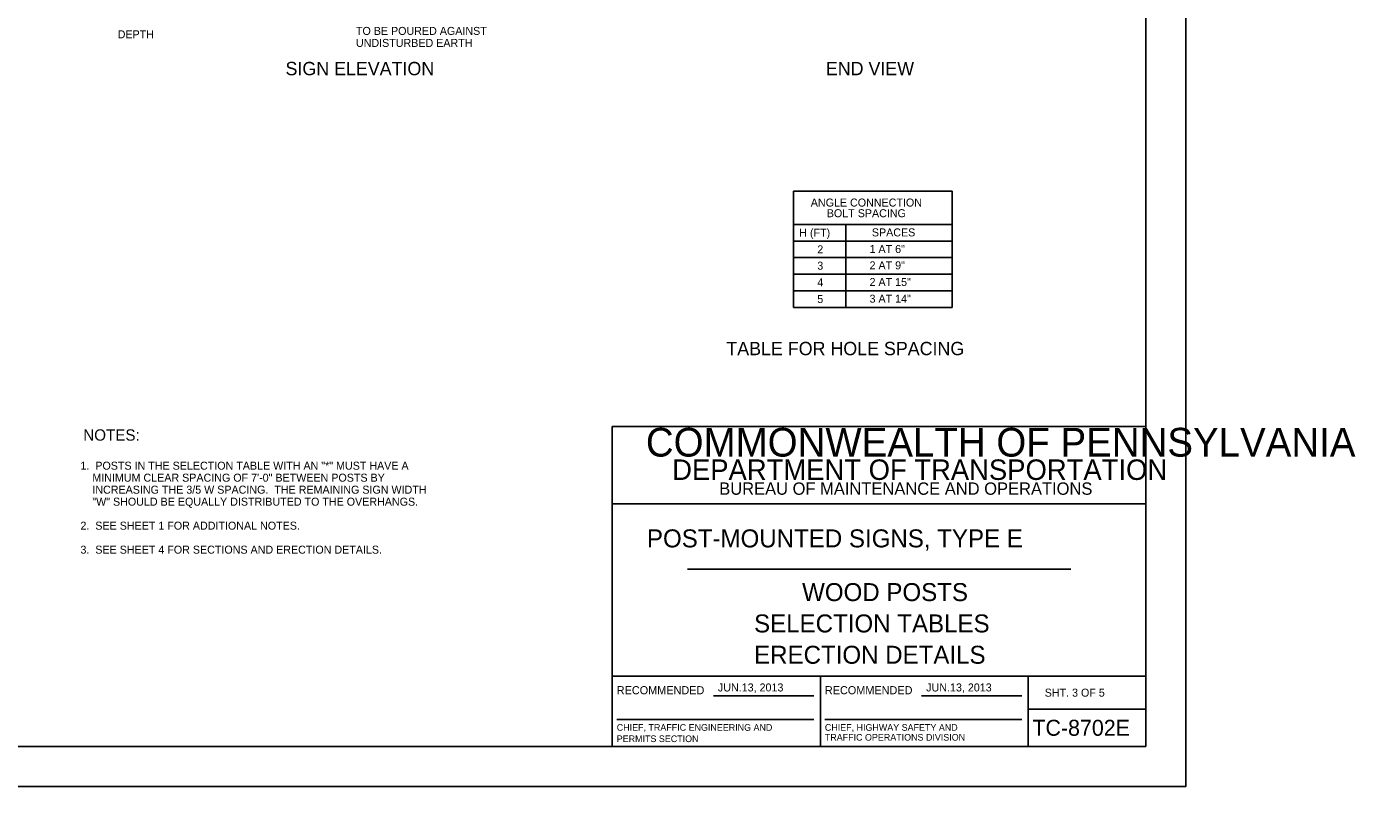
# Model space of a CAD drawing. Extents: x -2340 to 628, y -879 to 309.
# Drawn here: x 130.1 to 628.2, y -284.6 to 0.5 of the extents above; entities that cross this region are included whole.
import ezdxf

# ---------------------------------------------------------------- set-up
doc = ezdxf.new("R2010")
doc.units = 0
for name, color, linetype in [('Level 1', 7, 'Continuous'), ('Level 2', 7, 'Continuous'), ('Level 3', 7, 'Continuous'), ('Level 4', 7, 'Continuous'), ('PLT-BNDY', 7, 'Continuous')]:
    doc.layers.add(name, color=color, linetype=linetype)

msp = doc.modelspace()

# ---------------------------------------------------------------- linework, layer by layer
at = {"layer": 'Level 1'}
for p, q in [((549.61, -269.56), (549.61, 294.44)), ((349.61, -269.56), (349.61, -149.56)), ((349.61, -149.56), (549.61, -149.56)), ((549.61, -178.56), (349.61, -178.56)), ((377.86, -203.06), (521.49, -203.06)), ((349.61, -243.19), (549.61, -243.19)), ((427.61, -243.19), (427.61, -269.56)), ((505.49, -269.56), (505.49, -243.19)), ((387.55, -250.62), (425.17, -250.62)), ((465.55, -250.62), (503.17, -250.62)), ((505.49, -255.56), (549.61, -255.56)), ((351.3, -259.51), (425.17, -259.51)), ((429.3, -259.51), (503.17, -259.51)), ((549.61, -269.56), (-236.39, -269.56)), ((-236.39, -269.56), (349.61, -269.56))]:
    msp.add_line(p, q, dxfattribs=at)
at = {"layer": 'Level 2'}
for p, q in [((477.05, -61.22), (417.55, -61.22)), ((417.55, -104.84), (417.55, -61.22)), ((477.05, -104.84), (477.05, -61.22)), ((477.05, -73.72), (417.55, -73.72)), ((437.11, -104.84), (437.11, -73.72)), ((477.05, -79.97), (417.55, -79.97)), ((477.05, -86.09), (417.55, -86.09)), ((477.05, -92.34), (417.55, -92.34)), ((477.05, -98.59), (417.55, -98.59)), ((477.05, -104.84), (417.55, -104.84))]:
    msp.add_line(p, q, dxfattribs=at)
at = {"layer": 'PLT-BNDY'}
msp.add_lwpolyline([(-276.39, 309.44), (564.61, 309.44), (564.61, -284.56), (-276.39, -284.56)], close=True, dxfattribs=at)

# ---------------------------------------------------------------- texts
at = {"layer": 'Level 1'}
for s, height, p in [('COMMONWEALTH OF PENNSYLVANIA', 10.7827, (362.21, -160.83)), ('DEPARTMENT OF TRANSPORTATION', 7.6838, (372.07, -169.58)), ('BUREAU OF MAINTENANCE AND OPERATIONS', 4.6252, (389.71, -175.15)), ('POST-MOUNTED SIGNS, TYPE E', 6.7492, (362.61, -194.89)), ('WOOD POSTS', 6.75, (420.77, -215.04)), ('SELECTION TABLES', 6.75, (402.77, -226.79)), ('ERECTION DETAILS', 6.75, (402.77, -238.54)), ('RECOMMENDED', 3.048, (351.3, -249.99)), ('RECOMMENDED', 3.048, (429.3, -249.99)), ('SHT. 3 OF 5', 3, (511.7, -250.88)), ('CHIEF, TRAFFIC ENGINEERING AND', 2.5, (351.3, -263.68)), ('CHIEF, HIGHWAY SAFETY AND', 2.5, (429.3, -263.68)), ('TC-8702E', 6, (507.09, -265.56)), ('PERMITS SECTION', 2.5, (351.3, -267.93)), ('TRAFFIC OPERATIONS DIVISION', 2.5, (429.3, -267.38))]:
    msp.add_text(s, height=height, dxfattribs=at).set_placement(p)
at = {"layer": 'Level 2'}
for p in [(389.22, -248.93), (467.29, -248.93)]:
    msp.add_text('JUN.13, 2013', height=3, dxfattribs=at).set_placement(p)
at = {"layer": 'Level 3'}
for s, height, p in [('TO BE POURED AGAINST ', 3, (253.54, -2.65)), ('DEPTH', 3, (164.24, -3.92)), ('UNDISTURBED EARTH', 3, (253.54, -7.15)), ('SIGN ELEVATION', 5, (227.14, -17.77)), ('END VIEW', 5, (429.68, -17.77)), ('ANGLE CONNECTION', 3, (424.02, -67.04)), ('BOLT SPACING', 3, (430.02, -71.04)), ('H (FT)', 3, (419.71, -78.34)), ('SPACES', 3, (446.92, -78.23)), ('2', 3, (426.46, -84.59)), ('1 AT 6"', 3, (446.05, -84.47)), ('3', 3, (426.46, -90.72)), ('2 AT 9"', 3, (446.05, -90.59)), ('4', 3, (426.46, -96.97)), ('2 AT 15"', 3, (446.05, -96.84)), ('5', 3, (426.46, -103.22)), ('3 AT 14"', 3, (446.05, -103.09)), ('TABLE FOR HOLE SPACING', 5, (392.37, -122.79)), ('NOTES:', 4.25, (151.34, -154.85))]:
    msp.add_text(s, height=height, dxfattribs=at).set_placement(p)
at = {"layer": 'Level 4'}
for s, p in [('1.  POSTS IN THE SELECTION TABLE WITH AN "*" MUST HAVE A', (150.28, -165.74)), ('    MINIMUM CLEAR SPACING OF 7\'-0" BETWEEN POSTS BY', (150.28, -170.24)), ('    INCREASING THE 3/5 W SPACING.  THE REMAINING SIGN WIDTH', (150.28, -174.74)), ('    "W" SHOULD BE EQUALLY DISTRIBUTED TO THE OVERHANGS.', (150.28, -179.24)), ('2.  SEE SHEET 1 FOR ADDITIONAL NOTES.', (150.28, -188.24)), ('3.  SEE SHEET 4 FOR SECTIONS AND ERECTION DETAILS.', (150.28, -197.24))]:
    msp.add_text(s, height=3, dxfattribs=at).set_placement(p)

doc.saveas('drawing.dxf')
